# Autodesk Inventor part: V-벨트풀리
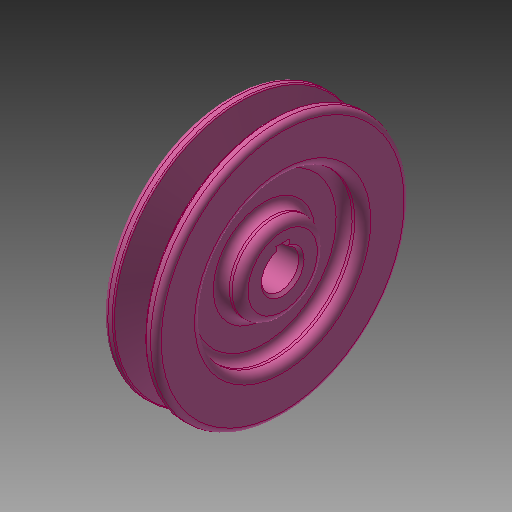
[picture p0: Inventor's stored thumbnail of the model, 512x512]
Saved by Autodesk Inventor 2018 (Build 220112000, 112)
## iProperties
Created: 2020-05
Part Number: V-벨트풀리
Material: 알루미늄 6061
Document SubType Name: Modeling
Designer: mduedu
Density: 1 g/cm^3
Appearance: 분홍색
Author: mduedu
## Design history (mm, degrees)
sketch "스케치1"
  geometry: L1 (-10, 0)-(10, 0); L2 (10, 47.5)-(-10, 47.5); L3 (-5.976, 47.5)-(-2.154, 35); L4 (-2.154, 35)-(2.154, 35); L5 (2.154, 35)-(5.976, 47.5); L6 (0, 0)-(0, 47.5); L7 (-10, 30)-(-3, 30); L8 (-3, 30)-(-3, 16); L9 (-3, 16)-(-10, 16); L10 (-10, 47.5)-(-10, 30); L11 (-10, 16)-(-10, 0); L12 (10, 30)-(3, 30); L13 (3, 30)-(3, 16); L14 (3, 16)-(10, 16); L15 (10, 0)-(10, 16); L16 (10, 30)-(10, 47.5); L17 (-4.6, 43)-(4.6, 43); 2 further points
  constraints: 34 end point, 6 parallel, 6 perpendicular, 4 point on line, 4 symmetric about line, 3 midpoint, 2 horizontal, 1 coincident, 1 collinear, 1 equal length, 1 vertical alignment
  dimensions: "d0" = 95 diameter of L2 L1; "d2" = 20 distance between parallel lines of L16 L10; "d3" = 6 distance between parallel lines of L13 L8; "d4" = 32 diameter of L14 L1; "d5" = 60 diameter of L12 L1; "d6" = 4.5 distance between parallel lines of L17 L2; "d7" = 8 distance between parallel lines of L4 L17; "d8" = 34 deg angle of L5 L3; "d9" = 9.2 distance of L17.start L17.end
revolve "회전1" sketch "스케치1" stored, may be unused: angle "d10" = 90 deg
sketch "스케치2"
  geometry: L1 (-2.5, 6.538)-(2.5, 6.538); L2 (2.5, 6.538)-(2.5, 9.3); L3 (2.5, 9.3)-(-2.5, 9.3); L4 (-2.5, 9.3)-(-2.5, 6.538); A1 r 7 centre (0, 0) between (-2.5, 6.538) and (2.5, 6.538); 1 further point
  constraints: 8 end point, 2 parallel, 2 point on circle, 1 centre point, 1 coincident, 1 horizontal, 1 perpendicular
  dimensions: "d11" = 14 diameter of A1; "d13" = 16.3 dimension on A1 L3; "d14" = 5 distance of L2.end L3.end
extrude "돌출1" cut sketch "스케치2" extent not by distance; stored distance "d15" = 10; taper "d16" = 0 deg
chamfer "모따기1" distance "d17" = 1; stored, may be unused: second distance "d18" = 2, angle "d19" = 45 deg
fillet "모깎기1" dims "d20" = 3
fillet "모깎기2" dims "d21" = 2
fillet "모깎기3" dims "d22" = 1
fillet "모깎기4" dims "d23" = 0.5
fillet "모깎기5" dims "d24" = 3
node "솔리드1"
